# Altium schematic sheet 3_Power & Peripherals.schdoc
size 309 x 223 mm; Symbol: Artery_A4; Device: Artery_A4; @Project Name: AT-START-M412; @Page Count: 4; @Create Date: 2024-06-20; Company: Artery Technology; Drawed: SD; Version: 1.0; Page Size: A4; @Update Date: 2024-09-05; @Page No: 3; @Schematic Name: AT-START-M412-V1.0; @Page Name: Power &amp; Peripherals; @Board Name: AT-START-M412-V1.0; @Create Time: 16:55:15; @Update Time: 09:48:56
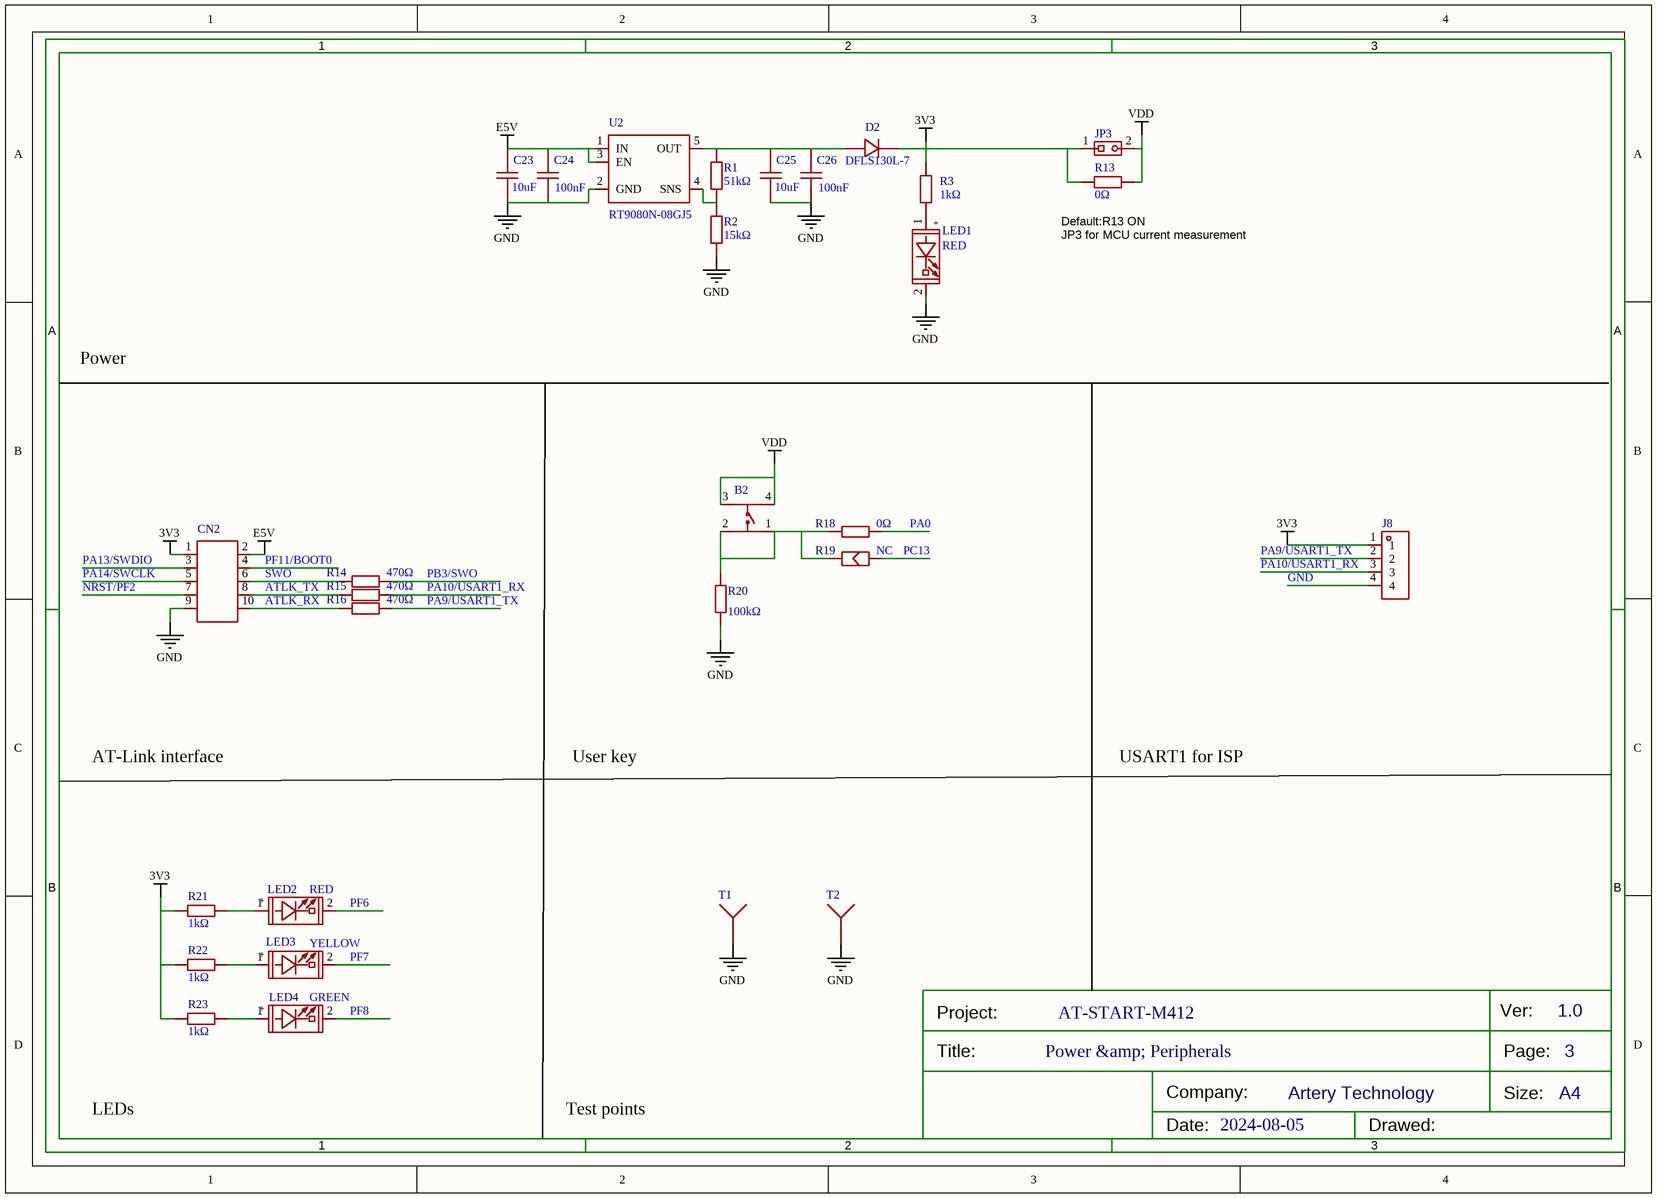
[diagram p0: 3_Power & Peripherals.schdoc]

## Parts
B2  TSA063G60-250  [KEY-SMD_4P-L6.1-W6.1-P4.50-LS9.0]  (value not drawn)
C23  10uF  [C0603]  (value not drawn)
C24  100nF  [C0603]  (value not drawn)
C25  10uF  [C0603]  (value not drawn)
C26  100nF  [C0603]  (value not drawn)
CN2  CON10  [HDR2X5]  (value not drawn)
D2  DFLS130L-7  [POWERDI-123_L2.8-W1.8-LS3.7-RD]  (value not drawn)
J8  PZ2.54-1*4-WZ  [HDR-TH_4P-P2.54-H-M-W7.7-P]  (value not drawn)
JP3  1X2P_2.54M  [HDR1X2]  (value not drawn)
LED1  RED  [LED0603]  (value not drawn)
LED2  RED  [LED0603]  (value not drawn)
LED3  YELLOW  [LED0603]  (value not drawn)
LED4  GREEN  [LED0603]  (value not drawn)
R1  51kΩ  [R0603]  (value not drawn)
R2  15kΩ  [R0603]  (value not drawn)
R3  1kΩ  [R0603]  (value not drawn)
R13  0Ω  [SB-PAD_2]  (value not drawn)
R14  470Ω  [R0603]  (value not drawn)
R15  470Ω  [R0603]  (value not drawn)
R16  470Ω  [R0603]  (value not drawn)
R18  0Ω  [SB-PAD_2]  (value not drawn)
R19  NC  [SB-PAD_2]  (value not drawn)
R20  100kΩ  [R0603]  (value not drawn)
R21  1kΩ  [R0603]  (value not drawn)
R22  1kΩ  [R0603]  (value not drawn)
R23  1kΩ  [R0603]  (value not drawn)
T1  Test point  [TestPoint]  (value not drawn)
T2  Test point  [TestPoint]  (value not drawn)
U2  RT9080N-08GJ5  [SOT-23-5]  (value not drawn)

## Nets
3V3: CN2.1 D2.1 J8.1 JP3.1 R3.2 R13.2 R21.2 R22.2 R23.2
E5V: C23.1 C24.1 CN2.2 U2.1(IN) U2.3(EN)
GND: C23.2 C24.2 C25.2 C26.2 CN2.9 J8.4 LED1.2(CATHODE) R2.2 R20.2 T1.1 T2.1 U2.2(GND)
VDD: B2.3 B2.4 JP3.2 R13.1
ATLK_RX: CN2.10 R16.2
ATLK_TX: CN2.8 R15.2
NRST/PF2: CN2.7
PA0: R18.1
PA9/USART1_TX: J8.2 R16.1
PA10/USART1_RX: J8.3 R15.1
PA13/SWDIO: CN2.3
PA14/SWCLK: CN2.5
PB3/SWO: R14.1
PC13: R19.1
PF6: LED2.2(CATHODE)
PF7: LED3.2(CATHODE)
PF8: LED4.2(CATHODE)
PF11/BOOT0: CN2.4
SWO: CN2.6 R14.2
NetB2_1: B2.1 B2.2 R18.2 R19.2 R20.1
NetC25_1: C25.1 C26.1 D2.2 R1.1 U2.5(OUT)
NetLED1_1: LED1.1(ANODE) R3.1
NetLED2_1: LED2.1(ANODE) R21.1
NetLED3_1: LED3.1(ANODE) R22.1
NetLED4_1: LED4.1(ANODE) R23.1
NetR1_2: R1.2 R2.1 U2.4(SNS)

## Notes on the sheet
- (near R13) JP3 for MCU current measurement
- (near R13) Default:R13 ON
- Power
- AT-Link interface
- User key
- USART1 for ISP
- AT-START-M412
- LEDs
- Test points
- 2024-08-05

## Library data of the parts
B2 = TSA063G60-250: 电路结构:单刀单掷;按钮形状:圆形按钮;作用力:250gf;安装方式:立贴;开关长度:6.1mm;开关宽度:6.1mm;开关高度:6mm;带支架:不带;触点电流:50mA;额定电压(DC):12V;绝缘电阻:100MΩ;带灯:无;机械寿命:5万次;; Manufacturer: BRIGHT(博瑞泰); Add into BOM: yes; Circuit: 单刀单掷; Actuator Style: 圆形按钮; Operating Force: 250gf; Switch Length: 6.1mm; Switch Height: 6mm; Strike Gundam: 不带; Contact Current: 50mA; Voltage Rating (DC): 12V; Insulation Resistance: 100MΩ; Actuator/Cap Color: 黑色; With Lamp: 无; Pin Style: 鸥翼型; Mechanical Life: 5万次; Origin Footprint: KEY_SOP_6*6
C23 C25 = CL10A106KP8NNNC: 容值:10uF;精度:±10%;额定电压:10V;材质(温度系数):X5R;; Manufacturer: SAMSUNG(三星); Add into BOM: yes; Tolerance: ±10%; Voltage Rated: 10V; Temperature Coefficient: X5R; Origin Footprint: 0603_C-M
C24 C26 = CC0603KRX7R9BB104: 容值:100nF;精度:±10%;额定电压:50V;材质(温度系数):X7R;; Manufacturer: YAGEO(国巨); Add into BOM: yes; Tolerance: ±10%; Voltage Rated: 50V; Temperature Coefficient: X7R; Origin Footprint: 0603_C-M
CN2 = CON10: 简易牛角DC3-10P 双排直插针 2.54mm 2*5P双排 黑色; Symbol: CON10A_0; Add into BOM: yes
D2 = DFLS130L-7: 正向压降(Vf):310mV@1A;直流反向耐压(Vr):30V;平均整流电流(Io):1A;; Manufacturer: DIODES(美台); Add into BOM: yes; Reverse Voltage (Vr): 30V; Average Rectified Current (Io): 1A; Origin Footprint: SOD-123
J8 = PZ2.54-1*4-WZ: 插针结构:1x4P;间距:2.54mm;安装类型:弯插;排数:单排;总PIN位数:4P;触头镀层:金;; Manufacturer: ZHOURI(洲日); Add into BOM: yes; Pin Structure: 1x4P; Pitch: 2.54mm; Origin Footprint: HDR1X4
JP3 = 1X2P_2.54M: Symbol: 1X2P,Male,DIP_2.54; Origin Footprint 2: SIP_2P; Add into BOM: yes; Check: true
LED1 LED2 = RED: 贴片LED 红色  0603; Symbol: RED,SMD0603; Add into BOM: yes
LED3 = YELLOW: 贴片LED 黄色 0603; Symbol: YELLOW,SMD0603; Add into BOM: yes
LED4 = GREEN: 贴片LED 绿色 0603; Symbol: GREEN,SMD0603; Add into BOM: yes
R1 = 0603WAF5102T5E: 电阻类型:厚膜电阻;阻值:51kΩ;精度:±1%;功率:100mW;最大工作电压:75V;温度系数:±100ppm/℃;; Manufacturer: UNI-ROYAL(厚声); Add into BOM: yes; Tolerance: ±1%; Power(Watts): 100mW; Overload Voltage (Max): 75V
R2 = 0603WAF1502T5E: 电阻类型:厚膜电阻;阻值:15kΩ;精度:±1%;功率:100mW;最大工作电压:75V;温度系数:±100ppm/℃;; Manufacturer: UNI-ROYAL(厚声); Add into BOM: yes; Tolerance: ±1%; Power(Watts): 100mW; Overload Voltage (Max): 75V
R3 R21-R23 = 0603WAF1001T5E: 电阻类型:厚膜电阻;阻值:1kΩ;精度:±1%;功率:100mW;最大工作电压:75V;温度系数:±100ppm/℃;; Manufacturer: UNI-ROYAL(厚声); Add into BOM: yes; Tolerance: ±1%; Power(Watts): 100mW; Overload Voltage (Max): 75V
R13 R18 = 0603WAF0000T5E: 电阻类型:厚膜电阻;阻值:0Ω;精度:±1%;功率:100mW;最大工作电压:75V;; Manufacturer: UNI-ROYAL(厚声); Add into BOM: yes; Tolerance: ±1%; Power(Watts): 100mW; Overload Voltage (Max): 75V; Origin Footprint: SB-PAD
R14-R16 = 0603WAF4700T5E: 电阻类型:厚膜电阻;阻值:470Ω;精度:±1%;功率:100mW;最大工作电压:75V;温度系数:±100ppm/℃;; Manufacturer: UNI-ROYAL(厚声); Add into BOM: yes; Tolerance: ±1%; Power(Watts): 100mW; Overload Voltage (Max): 75V; Origin Footprint: 0603_R-M
R19 = SB_PAD: 贴片电阻0R,1/10W,5%,0603; Symbol: SB-PAD; Convert to PCB: yes
R20 = 0603WAF1003T5E: 电阻类型:厚膜电阻;阻值:100kΩ;精度:±1%;功率:100mW;最大工作电压:75V;温度系数:±100ppm/℃;; Manufacturer: UNI-ROYAL(厚声); Add into BOM: yes; Tolerance: ±1%; Power(Watts): 100mW; Overload Voltage (Max): 75V
T1 T2 = Test point: Keystone 美标塑料PCB板测试针环 黑色中号（TP-5006）; Symbol: Socket; Add into BOM: yes
U2 = RT9080N-08GJ5: Add into BOM: yes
